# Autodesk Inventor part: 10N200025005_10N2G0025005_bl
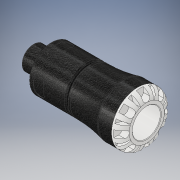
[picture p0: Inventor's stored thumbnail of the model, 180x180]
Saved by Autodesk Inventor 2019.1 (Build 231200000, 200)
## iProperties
Created: 2016-12
Part Number: 10N200025005_10N2G0025005_bl
Material: PVC-Piping
Description: PLASSON MALE ADAPTOR 25X1/2" SERIES 1
Document SubType Name: Modeling
Designer: KIM
Mass: 61.7504 g
Surface Area: 140.097 cm^2
Volume: 44.1074 cm^3
Density: 1.4 g/cm^3
Appearance: Black Cast
Author: KIM
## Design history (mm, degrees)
derived "10N20.ipt"
feature "Solid1::10N20.ipt" dims "ScaleForDerivedMember" = 10
tag "TaggingFeature1"
body "Solid1"
other parameters: "d0" = 101 [user parameter], "d1" = 20.16 [user parameter], "d2" = 25 [user parameter], "d3" = 31.25 [user parameter], "d4" = 47 [user parameter], "d6" = 48 [user parameter], "d8" = 39.95 [user parameter], "d13" = 6.3 [user parameter], "d14" = 6.3 [user parameter], "d15" = 0 [user parameter], "d17" = 360 deg [user parameter], "d19" = 8 deg [user parameter], "d20" = 0.5 [user parameter], "d21" = 0.5 [user parameter], "d22" = 8 deg [user parameter], "d24" = 0 [user parameter], "d26" = 360 deg [user parameter], "d32" = 0.925 [user parameter], "d33" = 4.7 [user parameter], "d34" = 20.955 [user parameter], "d35" = 5 [user parameter], "d38" = 16 [user parameter], "d39" = 0.62865 [user parameter], "d42" = 8.75 [user parameter], "d43" = 5.75 [user parameter], "d45" = 12.348 [user parameter], "d46" = 0 [user parameter], "d59" = 360 deg [user parameter], "d61" = 7.4375 [user parameter], "d62" = 0.5 [user parameter], "d64" = 0 [user parameter], "d65" = 0.47 [user parameter], "d69" = 2 [user parameter], "d70" = 1.515 [user parameter], "d71" = 3 [user parameter], "d73" = 1 [user parameter], "d_" = 25 [user parameter], "E_" = 47 [user parameter], "H_" = 101 [user parameter], "l_" = 48 [user parameter], "R_" = 20.955 [user parameter], "l_2" = 16 [user parameter], "d9" = 7.875 [user parameter], "d11" = 47 [user parameter], "d12" = 31.25 [user parameter]
